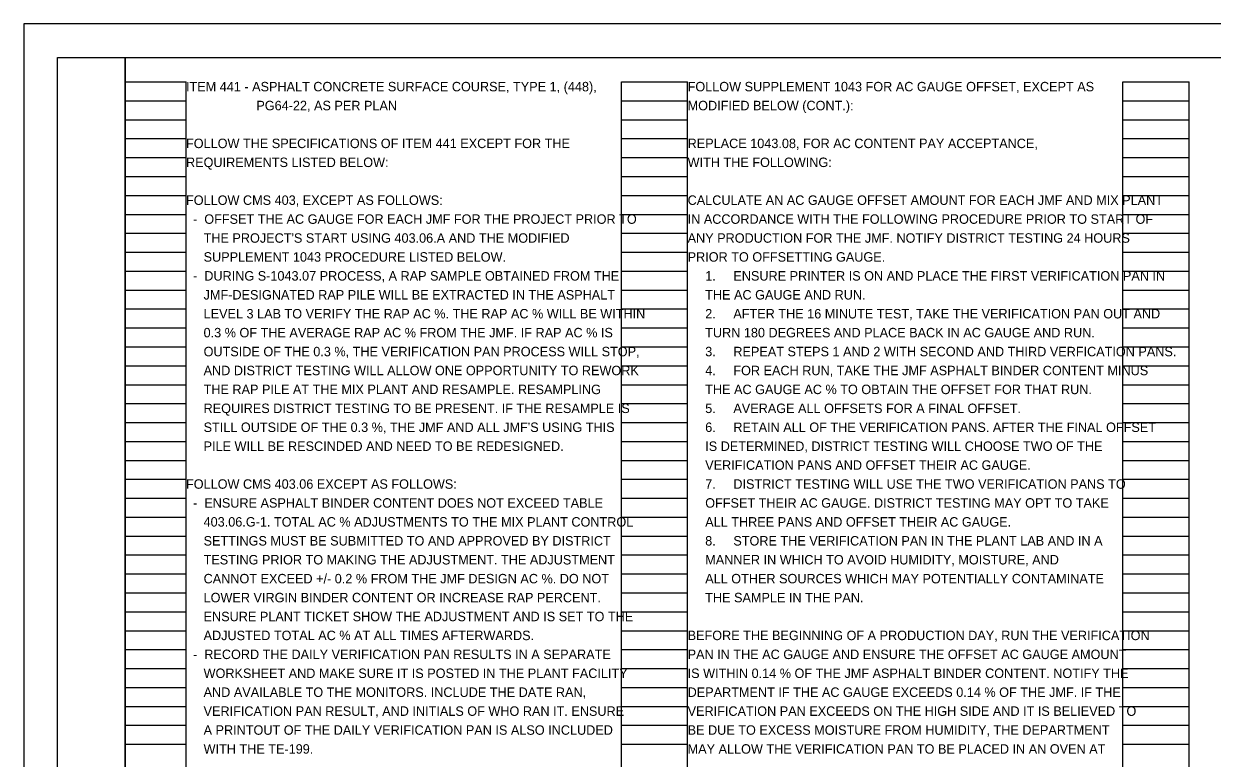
# Model space of a CAD drawing. Extents: x 0 to 34, y 0 to 22.
# Drawn here: x 0 to 17.58, y 11.13 to 22 of the extents above; entities that cross this region are included whole.
import ezdxf

# ---------------------------------------------------------------- set-up
doc = ezdxf.new("R2010")
doc.units = 0
for name, color, linetype in [('SH_Border', 7, 'Continuous'), ('SH_Cut_Line', 7, 'Continuous'), ('SH_Data', 7, 'Continuous'), ('SH_Text', 7, 'Continuous')]:
    doc.layers.add(name, color=color, linetype=linetype)

msp = doc.modelspace()

# ---------------------------------------------------------------- linework, layer by layer
at = {"layer": 'SH_Border'}
for points in [[(0.5, 21.5), (1.5, 21.5), (1.5, 0.5), (0.5, 0.5)], [(1.5, 21.5), (33.5, 21.5), (33.5, 0.5), (1.5, 0.5)]]:
    msp.add_lwpolyline(points, close=True, dxfattribs=at)
at = {"layer": 'SH_Cut_Line'}
msp.add_lwpolyline([(0, 0), (34, 0), (34, 22), (0, 22)], close=True, dxfattribs=at)
at = {"layer": 'SH_Data'}
for p, q in [((1.5, 0.98), (1.5, 21.14)), ((1.5, 21.14), (2.4, 21.14)), ((2.4, 0.98), (2.4, 21.14)), ((8.84, 0.98), (8.84, 21.14)), ((8.84, 21.14), (9.82, 21.14)), ((9.82, 0.98), (9.82, 21.14)), ((16.26, 0.98), (16.26, 21.14)), ((16.26, 21.14), (17.24, 21.14)), ((17.24, 0.98), (17.24, 21.14)), ((1.5, 20.86), (2.4, 20.86)), ((8.84, 20.86), (9.82, 20.86)), ((16.26, 20.86), (17.24, 20.86)), ((1.5, 20.58), (2.4, 20.58)), ((8.84, 20.58), (9.82, 20.58)), ((16.26, 20.58), (17.24, 20.58)), ((1.5, 20.3), (2.4, 20.3)), ((8.84, 20.3), (9.82, 20.3)), ((16.26, 20.3), (17.24, 20.3)), ((1.5, 20.02), (2.4, 20.02)), ((8.84, 20.02), (9.82, 20.02)), ((16.26, 20.02), (17.24, 20.02)), ((1.5, 19.74), (2.4, 19.74)), ((8.84, 19.74), (9.82, 19.74)), ((16.26, 19.74), (17.24, 19.74)), ((1.5, 19.46), (2.4, 19.46)), ((8.84, 19.46), (9.82, 19.46)), ((16.26, 19.46), (17.24, 19.46)), ((1.5, 19.18), (2.4, 19.18)), ((8.84, 19.18), (9.82, 19.18)), ((16.26, 19.18), (17.24, 19.18)), ((1.5, 18.9), (2.4, 18.9)), ((8.84, 18.9), (9.82, 18.9)), ((16.26, 18.9), (17.24, 18.9)), ((1.5, 18.62), (2.4, 18.62)), ((8.84, 18.62), (9.82, 18.62)), ((16.26, 18.62), (17.24, 18.62)), ((1.5, 18.34), (2.4, 18.34)), ((8.84, 18.34), (9.82, 18.34)), ((16.26, 18.34), (17.24, 18.34)), ((1.5, 18.06), (2.4, 18.06)), ((8.84, 18.06), (9.82, 18.06)), ((16.26, 18.06), (17.24, 18.06)), ((1.5, 17.78), (2.4, 17.78)), ((8.84, 17.78), (9.82, 17.78)), ((16.26, 17.78), (17.24, 17.78)), ((1.5, 17.5), (2.4, 17.5)), ((8.84, 17.5), (9.82, 17.5)), ((16.26, 17.5), (17.24, 17.5)), ((1.5, 17.22), (2.4, 17.22)), ((8.84, 17.22), (9.82, 17.22)), ((16.26, 17.22), (17.24, 17.22)), ((1.5, 16.94), (2.4, 16.94)), ((8.84, 16.94), (9.82, 16.94)), ((16.26, 16.94), (17.24, 16.94)), ((1.5, 16.66), (2.4, 16.66)), ((8.84, 16.66), (9.82, 16.66)), ((16.26, 16.66), (17.24, 16.66)), ((1.5, 16.38), (2.4, 16.38)), ((8.84, 16.38), (9.82, 16.38)), ((16.26, 16.38), (17.24, 16.38)), ((1.5, 16.1), (2.4, 16.1)), ((8.84, 16.1), (9.82, 16.1)), ((16.26, 16.1), (17.24, 16.1)), ((1.5, 15.82), (2.4, 15.82)), ((8.84, 15.82), (9.82, 15.82)), ((16.26, 15.82), (17.24, 15.82)), ((1.5, 15.54), (2.4, 15.54)), ((8.84, 15.54), (9.82, 15.54)), ((16.26, 15.54), (17.24, 15.54)), ((1.5, 15.26), (2.4, 15.26)), ((8.84, 15.26), (9.82, 15.26)), ((16.26, 15.26), (17.24, 15.26)), ((1.5, 14.98), (2.4, 14.98)), ((8.84, 14.98), (9.82, 14.98)), ((16.26, 14.98), (17.24, 14.98)), ((1.5, 14.7), (2.4, 14.7)), ((8.84, 14.7), (9.82, 14.7)), ((16.26, 14.7), (17.24, 14.7)), ((1.5, 14.42), (2.4, 14.42)), ((8.84, 14.42), (9.82, 14.42)), ((16.26, 14.42), (17.24, 14.42)), ((1.5, 14.14), (2.4, 14.14)), ((8.84, 14.14), (9.82, 14.14)), ((16.26, 14.14), (17.24, 14.14)), ((1.5, 13.86), (2.4, 13.86)), ((8.84, 13.86), (9.82, 13.86)), ((16.26, 13.86), (17.24, 13.86)), ((1.5, 13.58), (2.4, 13.58)), ((8.84, 13.58), (9.82, 13.58)), ((16.26, 13.58), (17.24, 13.58)), ((1.5, 13.3), (2.4, 13.3)), ((8.84, 13.3), (9.82, 13.3)), ((16.26, 13.3), (17.24, 13.3)), ((1.5, 13.02), (2.4, 13.02)), ((8.84, 13.02), (9.82, 13.02)), ((16.26, 13.02), (17.24, 13.02)), ((1.5, 12.74), (2.4, 12.74)), ((8.84, 12.74), (9.82, 12.74)), ((16.26, 12.74), (17.24, 12.74)), ((1.5, 12.46), (2.4, 12.46)), ((8.84, 12.46), (9.82, 12.46)), ((16.26, 12.46), (17.24, 12.46)), ((1.5, 12.18), (2.4, 12.18)), ((8.84, 12.18), (9.82, 12.18)), ((16.26, 12.18), (17.24, 12.18)), ((1.5, 11.9), (2.4, 11.9)), ((8.84, 11.9), (9.82, 11.9)), ((16.26, 11.9), (17.24, 11.9)), ((1.5, 11.62), (2.4, 11.62)), ((8.84, 11.62), (9.82, 11.62)), ((16.26, 11.62), (17.24, 11.62)), ((1.5, 11.34), (2.4, 11.34)), ((8.84, 11.34), (9.82, 11.34)), ((16.26, 11.34), (17.24, 11.34))]:
    msp.add_line(p, q, dxfattribs=at)

# ---------------------------------------------------------------- texts
at = {"layer": 'SH_Text'}
for s, p in [('ITEM 441 - ASPHALT CONCRETE SURFACE COURSE, TYPE 1, (448),', (2.4, 21)), ('FOLLOW SUPPLEMENT 1043 FOR AC GAUGE OFFSET, EXCEPT AS', (9.82, 21)), ('                    PG64-22, AS PER PLAN', (2.4, 20.72)), ('MODIFIED BELOW (CONT.):', (9.82, 20.72)), ('FOLLOW THE SPECIFICATIONS OF ITEM 441 EXCEPT FOR THE', (2.4, 20.16)), ('REPLACE 1043.08, FOR AC CONTENT PAY ACCEPTANCE,', (9.82, 20.16)), ('REQUIREMENTS LISTED BELOW:', (2.4, 19.88)), ('WITH THE FOLLOWING:', (9.82, 19.88)), ('FOLLOW CMS 403, EXCEPT AS FOLLOWS:', (2.4, 19.32)), ('CALCULATE AN AC GAUGE OFFSET AMOUNT FOR EACH JMF AND MIX PLANT', (9.82, 19.32)), ('  -  OFFSET THE AC GAUGE FOR EACH JMF FOR THE PROJECT PRIOR TO', (2.4, 19.04)), ('IN ACCORDANCE WITH THE FOLLOWING PROCEDURE PRIOR TO START OF', (9.82, 19.04)), ("     THE PROJECT'S START USING 403.06.A AND THE MODIFIED", (2.4, 18.76)), ('ANY PRODUCTION FOR THE JMF. NOTIFY DISTRICT TESTING 24 HOURS', (9.82, 18.76)), ('     SUPPLEMENT 1043 PROCEDURE LISTED BELOW.', (2.4, 18.48)), ('PRIOR TO OFFSETTING GAUGE.', (9.82, 18.48)), ('  -  DURING S-1043.07 PROCESS, A RAP SAMPLE OBTAINED FROM THE', (2.4, 18.2)), ('     1.     ENSURE PRINTER IS ON AND PLACE THE FIRST VERIFICATION PAN IN', (9.82, 18.2)), ('     JMF-DESIGNATED RAP PILE WILL BE EXTRACTED IN THE ASPHALT', (2.4, 17.92)), ('     THE AC GAUGE AND RUN.', (9.82, 17.92)), ('     LEVEL 3 LAB TO VERIFY THE RAP AC %. THE RAP AC % WILL BE WITHIN', (2.4, 17.64)), ('     2.     AFTER THE 16 MINUTE TEST, TAKE THE VERIFICATION PAN OUT AND', (9.82, 17.64)), ('     0.3 % OF THE AVERAGE RAP AC % FROM THE JMF. IF RAP AC % IS', (2.4, 17.36)), ('     TURN 180 DEGREES AND PLACE BACK IN AC GAUGE AND RUN.', (9.82, 17.36)), ('     OUTSIDE OF THE 0.3 %, THE VERIFICATION PAN PROCESS WILL STOP,', (2.4, 17.08)), ('     3.     REPEAT STEPS 1 AND 2 WITH SECOND AND THIRD VERFICATION PANS.', (9.82, 17.08)), ('     AND DISTRICT TESTING WILL ALLOW ONE OPPORTUNITY TO REWORK', (2.4, 16.8)), ('     4.     FOR EACH RUN, TAKE THE JMF ASPHALT BINDER CONTENT MINUS', (9.82, 16.8)), ('     THE RAP PILE AT THE MIX PLANT AND RESAMPLE. RESAMPLING', (2.4, 16.52)), ('     THE AC GAUGE AC % TO OBTAIN THE OFFSET FOR THAT RUN.', (9.82, 16.52)), ('     REQUIRES DISTRICT TESTING TO BE PRESENT. IF THE RESAMPLE IS', (2.4, 16.24)), ('     5.     AVERAGE ALL OFFSETS FOR A FINAL OFFSET.', (9.82, 16.24)), ("     STILL OUTSIDE OF THE 0.3 %, THE JMF AND ALL JMF'S USING THIS", (2.4, 15.96)), ('     6.     RETAIN ALL OF THE VERIFICATION PANS. AFTER THE FINAL OFFSET', (9.82, 15.96)), ('     PILE WILL BE RESCINDED AND NEED TO BE REDESIGNED.', (2.4, 15.68)), ('     IS DETERMINED, DISTRICT TESTING WILL CHOOSE TWO OF THE', (9.82, 15.68)), ('     VERIFICATION PANS AND OFFSET THEIR AC GAUGE.', (9.82, 15.4)), ('FOLLOW CMS 403.06 EXCEPT AS FOLLOWS:', (2.4, 15.12)), ('     7.     DISTRICT TESTING WILL USE THE TWO VERIFICATION PANS TO', (9.82, 15.12)), ('  -  ENSURE ASPHALT BINDER CONTENT DOES NOT EXCEED TABLE', (2.4, 14.84)), ('     OFFSET THEIR AC GAUGE. DISTRICT TESTING MAY OPT TO TAKE', (9.82, 14.84)), ('     403.06.G-1. TOTAL AC % ADJUSTMENTS TO THE MIX PLANT CONTROL', (2.4, 14.56)), ('     ALL THREE PANS AND OFFSET THEIR AC GAUGE.', (9.82, 14.56)), ('     SETTINGS MUST BE SUBMITTED TO AND APPROVED BY DISTRICT', (2.4, 14.28)), ('     8.     STORE THE VERIFICATION PAN IN THE PLANT LAB AND IN A', (9.82, 14.28)), ('     TESTING PRIOR TO MAKING THE ADJUSTMENT. THE ADJUSTMENT', (2.4, 14)), ('     MANNER IN WHICH TO AVOID HUMIDITY, MOISTURE, AND', (9.82, 14)), ('     CANNOT EXCEED +/- 0.2 % FROM THE JMF DESIGN AC %. DO NOT', (2.4, 13.72)), ('     ALL OTHER SOURCES WHICH MAY POTENTIALLY CONTAMINATE', (9.82, 13.72)), ('     LOWER VIRGIN BINDER CONTENT OR INCREASE RAP PERCENT.', (2.4, 13.44)), ('     THE SAMPLE IN THE PAN.', (9.82, 13.44)), ('     ENSURE PLANT TICKET SHOW THE ADJUSTMENT AND IS SET TO THE', (2.4, 13.16)), ('     ADJUSTED TOTAL AC % AT ALL TIMES AFTERWARDS.', (2.4, 12.88)), ('BEFORE THE BEGINNING OF A PRODUCTION DAY, RUN THE VERIFICATION', (9.82, 12.88)), ('  -  RECORD THE DAILY VERIFICATION PAN RESULTS IN A SEPARATE', (2.4, 12.6)), ('PAN IN THE AC GAUGE AND ENSURE THE OFFSET AC GAUGE AMOUNT', (9.82, 12.6)), ('     WORKSHEET AND MAKE SURE IT IS POSTED IN THE PLANT FACILITY', (2.4, 12.32)), ('IS WITHIN 0.14 % OF THE JMF ASPHALT BINDER CONTENT. NOTIFY THE', (9.82, 12.32)), ('     AND AVAILABLE TO THE MONITORS. INCLUDE THE DATE RAN,', (2.4, 12.04)), ('DEPARTMENT IF THE AC GAUGE EXCEEDS 0.14 % OF THE JMF. IF THE', (9.82, 12.04)), ('     VERIFICATION PAN RESULT, AND INITIALS OF WHO RAN IT. ENSURE', (2.4, 11.76)), ('VERIFICATION PAN EXCEEDS ON THE HIGH SIDE AND IT IS BELIEVED TO', (9.82, 11.76)), ('     A PRINTOUT OF THE DAILY VERIFICATION PAN IS ALSO INCLUDED', (2.4, 11.48)), ('BE DUE TO EXCESS MOISTURE FROM HUMIDITY, THE DEPARTMENT', (9.82, 11.48)), ('     WITH THE TE-199.', (2.4, 11.2)), ('MAY ALLOW THE VERIFICATION PAN TO BE PLACED IN AN OVEN AT', (9.82, 11.2))]:
    msp.add_text(s, height=0.14, dxfattribs=at).set_placement(p)

doc.saveas('drawing.dxf')
